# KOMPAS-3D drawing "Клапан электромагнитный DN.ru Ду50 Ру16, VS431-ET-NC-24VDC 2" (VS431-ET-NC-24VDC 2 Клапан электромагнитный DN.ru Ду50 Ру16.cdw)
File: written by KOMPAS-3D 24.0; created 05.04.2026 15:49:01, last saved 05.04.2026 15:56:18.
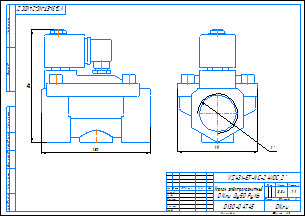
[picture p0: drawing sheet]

Document properties: c3d_UniqueCompID: ef56311e-7521-43dc-8291-0e6108b3d81d; Автор: artio; Класс точности: c; Знак неуказанной шероховатости: Шероховатость не задана; Рассекать на разрезах: Да; c3d_UniqueCompID: ef56311e-7521-43dc-8291-0e6108b3d81d; Автор: artio; Класс точности: c; Знак неуказанной шероховатости: Шероховатость не задана; Рассекать на разрезах: Да; c3d_UniqueCompID: ef56311e-7521-43dc-8291-0e6108b3d81d; Автор: artio; Класс точности: c; Знак неуказанной шероховатости: Шероховатость не задана; Рассекать на разрезах: Да; c3d_UniqueCompID: ef56311e-7521-43dc-8291-0e6108b3d81d; Автор: artio; Класс точности: c; Знак неуказанной шероховатости: Шероховатость не задана; Рассекать на разрезах: Да; c3d_UniqueCompID: ef56311e-7521-43dc-8291-0e6108b3d81d; Автор: artio; Класс точности: c; Знак неуказанной шероховатости: Шероховатость не задана; Рассекать на разрезах: Да; Автор: artio; Форматы листов документа: A3; Полное имя файла: VS431-ET-NC-24VDC 2 Клапан электромагнитный DN.ru Ду50 Ру16.m3d; Масса: 3.341; Наименование: Клапан электромагнитный DN.ru Ду50 Ру16; Количество листов документа: 1; Примечание: D130-04745

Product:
- Body: Тело 1  | qty 1
    Масса: 6.703651
- Part/product: Клапан электромагнитный DN.ru Ду50 Ру16  | designation VS431-ET-NC-24VDC 2
    Масса: 3.341
    Раздел спецификации: Прочие изделия
    Примечание: D130-04745
    additional columns: ef56311e-7521-43dc-8291-0e6108b3d81d; artio; c; Шероховатость не задана; Да

Views: Вид 1, Спереди
Referenced files in C:\Users\artio\OneDrive\Рабочий стол\Клапан электромагнитный DN.ru\VS431\VS431-ET-NC\: VS431-ET-NC-24VDC 3-4 Клапан электромагнитный DN.ru Ду20 Ру16.m3d, VS431-ET-NC-24VDC 2 Клапан электромагнитный DN.ru Ду50 Ру16.m3d, VS431-ET-NC-24VDC 3-4 Клапан электромагнитный DN.ru Ду20 Ру16.cdw
Referenced files in C:\Users\artio\OneDrive\Рабочий стол\Клапан электромагнитный DN.ru\VS431\VS431-ET-NC\VS431-ET-NC-24VDC\Ду50\: VS431-ET-NC-24VDC 2 Клапан электромагнитный DN.ru Ду50 Ру16.m3d
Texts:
  VS431-ET-NC-24VDC 2
  Клапан электромагнитный
  DN.ru Ду50 Ру16
  VS431-ET-NC-24VDC 2"
  VS431-ET-NC-24VDC 2"-
  Клапан электромагнитный DN.ru Ду50 Ру16
  VS431-ET-NC-24VDC 2 Клапан электромагнитный DN.ru Ду50 Ру16
Dimensions and other numbers on the sheet: 0; 3; 2; 4; 111; 1:1; 1; 3,34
